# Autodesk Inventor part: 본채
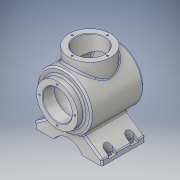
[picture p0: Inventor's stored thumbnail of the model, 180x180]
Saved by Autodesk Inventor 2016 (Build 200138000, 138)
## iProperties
Created: 2021-04
Part Number: 본채
Material: 알루미늄 6061
Document SubType Name: Modeling
Designer: pc-04
Density: 2.7 g/cm^3
Appearance: 알루미늄 - 평지
Mass: 1644.46 g
Surface Area: 1039.22 cm^2
Volume: 609.061 cm^3
Author: pc-04
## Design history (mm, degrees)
sketch "스케치1"
  geometry: L1 (0, 0)-(25.981, 0); L2 (62, 0)-(62, 10); L3 (62, 10)-(26.296, 35); L4 (26.296, 35)-(-26.296, 35); L5 (-26.296, 35)-(-62, 10); L6 (-62, 10)-(-62, 0); L7 (-62, 0)-(-25.981, 0); L8 (-25.981, 0)-(0, 0); L9 (25.981, 0)-(62, 0); A1 r 30 centre (0, -15) between (25.981, 0) and (-25.981, 0); 1 further point
  constraints: 18 end point, 4 collinear, 3 parallel, 2 horizontal, 2 perpendicular, 2 point on circle, 2 vertical alignment, 1 centre point, 1 midpoint, 1 point on line
  dimensions: "d0" = 124 distance between parallel lines of L2 L6; "d1" = 30 radius of A1; "d2" = 15 distance centre to line of A1 L1; "d3" = 10 distance from line of L7 L5.end; "d4" = 10 distance from line of L1 L2.end; "d5" = 55 deg angle of L5 L6; "d6" = 55 deg angle of L3 L2; "d22" = 35 distance between parallel lines of L9 L4
extrude "돌출1" new body sketch "스케치1" stored distance "d8" = 80; taper "d9" = 0 deg
sketch "스케치2"
  geometry: L1 (77, -60)-(77, 60); L2 (77, 60)-(115, 60); L3 (115, 60)-(115, 48); L4 (115, 48)-(127, 48); L5 (127, 48)-(127, -48.336); L6 (104, 60)-(104, 38); L7 (104, 38)-(117, 38); L8 (117, 38)-(117, -41.916); L9 (0, -40)-(0, 40) reference; L10 (0, 40)-(15, 40) reference; A1 r 113 centre (77, 53) between (77, -60) and (127, -48.336); A2 r 103 centre (77, 53) between (77, -50) and (117, -41.916); 1 further point
  constraints: 16 end point, 7 perpendicular, 4 point on circle, 3 point on line, 2 centre point, 1 vertical
  dimensions: "d10" = 100 diameter of L5 L1; "d11" = 76 diameter of L3 L1; "d12" = 120 distance of L1.start L1.end; "d13" = 103 radius of A2; "d14" = 113 radius of A1; "d15" = 12 distance between parallel lines of L4 L2; "d16" = 80 diameter of L8 L1; "d17" = 22 distance between parallel lines of L7 L2; "d18" = 77 distance between parallel lines of L9 L1; "d19" = 20 distance between parallel lines of L2 L10; "d20" = 54 diameter of L6 L1
revolve "회전1" sketch "스케치2" stored, may be unused: angle "d21" = 90 deg
sketch "스케치3"
  geometry: L1 (62, 0)-(25.981, 0) reference; L2 (0, 117)-(38, 117); L3 (38, 117)-(38, 142); L4 (38, 142)-(0, 142); L5 (0, 142)-(0, 117); 4 further points
  constraints: 8 end point, 2 parallel, 2 vertical alignment, 1 horizontal, 1 perpendicular, 1 other
  dimensions: "d29" = 142 distance between parallel lines of L1 L4; "d30" = 76 diameter of L3 L5; "d31" = 25 distance between parallel lines of L2 L4
revolve "회전3" sketch "스케치3" stored, may be unused: angle "d32" = 90 deg
sketch "스케치4"
  geometry: L1 (30, 117)-(38, 117) reference; L2 (38, 117)-(30, 117); L3 (30, 117)-(30, 109.496); L4 (30, 109.496)-(38, 109.496); L5 (38, 109.496)-(38, 117); L6 (0, -28.4)-(0, 170.4) reference; L7 (-38, 117)-(-30, 117); L8 (-30, 117)-(-30, 109.496); L9 (-30, 109.496)-(-38, 109.496); L10 (-38, 109.496)-(-38, 117); L11 (-38, 117)-(-30, 117) reference; A1 r 50 centre (0, 77) between (30, 117) and (38, 109.496) reference; 1 further point
  constraints: 16 end point, 4 parallel, 3 point on circle, 2 horizontal, 2 perpendicular, 1 point on line
  dimensions: "d33" = 8 distance between parallel lines of L5 L3; "d36" = 8 distance between parallel lines of L8 L10
revolve "회전4" stored, may be unused: angle "d34" = 90 deg
revolve "회전5" stored, may be unused: angle "d35" = 90 deg
revolve "회전6" stored, may be unused: angle "d37" = 90 deg
revolve "회전7" stored, may be unused: angle "d38" = 90 deg
hole "구멍1" diameter "d41" = 54; stored, may be unused: countersink angle "d45" = 90 deg, drill point angle "d47" = 0 deg; dims "d39" = 10, "d40" = 10, "d42" = 6, "d43" = 4, "d44" = 2, "d46" = 8
node "작업 평면2"
sketch "스케치5"
  geometry: L1 (-54, -27)-(-62, -27); L2 (-54, -13)-(-62, -13); L3 (-62, 40)-(-62, -40) reference; L4 (-26.694, -40)-(-62, -40) reference; C1 r 4.5 at (-54, -20); A1 r 7 centre (-54, -20) between (-54, -27) and (-54, -13); 1 further point
  constraints: 4 end point, 2 centre point, 2 horizontal, 2 point on circle, 2 point on line, 1 coincident, 1 parallel
  dimensions: "d49" = 14 diameter of A1; "d50" = 8 distance from line of L3 A1.centre; "d51" = 20 distance from line of A1.centre L4; "d52" = 8 distance of L1.start L1.end; "d53" = 9 diameter of C1
extrude "돌출2" cut sketch "스케치5" distance "d54" = 24; taper "d55" = 0 deg
extrude "돌출3" cut sketch "스케치5" stored distance "d56" = 24; taper "d57" = 0 deg
fillet "모깎기1" dims "d61" = 3
fillet "모깎기2" dims "d62" = 3
chamfer "모따기1" distance "d63" = 1; stored, may be unused: second distance "d64" = 2, angle "d65" = 45 deg
chamfer "모따기2" distance "d66" = 1; stored, may be unused: second distance "d67" = 2, angle "d68" = 45 deg
node "작업 평면6"
sketch "스케치8"
  geometry: L1 (50, 0)-(-50, 0); A1 r 50 centre (0, 0) between (50, 0) and (-50, 0) reference; 1 further point
  constraints: 2 end point, 2 horizontal, 2 point on circle
extrude "돌출6" join sketch "스케치8" distance "d79" = 5.5; taper "d80" = 0 deg
sketch "스케치9"
  geometry: C1 r 38 at (0, 0) reference; 2 further points
  constraints: 1 vertical alignment
  dimensions: "d81" = 32.5 distance of point (0, 32.5) C1.centre
hole "구멍2" sketch "스케치9" at (0, 32.5) diameter "d82" = 3.242; stored, may be unused: countersink angle "d86" = 90 deg, drill point angle "d88" = 118 deg; dims "d83" = 8, "d84" = 4, "d85" = 2, "d87" = 10
sketch "스케치10"
  geometry: 2 further points
  constraints: 1 vertical alignment
  dimensions: "d92" = 32.5 distance of point (0, 0) point (0, 32.5)
hole "구멍3" sketch "스케치10" at (0, 32.5) diameter "d93" = 3.242; stored, may be unused: countersink angle "d97" = 90 deg, drill point angle "d99" = 118 deg; dims "d94" = 8, "d95" = 4, "d96" = 2, "d98" = 10
node "솔리드1"
pattern_linear "직사각형 패턴1"
mirror "대칭1"
pattern_circular "원형 패턴1" dims angle "d90" = 360 deg
pattern_circular "원형 패턴2" dims angle "d101" = 360 deg
other parameters: "d78" = -115
